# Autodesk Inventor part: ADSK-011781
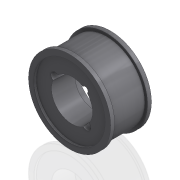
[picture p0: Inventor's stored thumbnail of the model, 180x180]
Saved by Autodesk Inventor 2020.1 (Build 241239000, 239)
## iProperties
Created: 1999-11
Part Number: ADSK-011781
Material: Acier (alliage faible hypertrempé)
Document SubType Name: Modeling
Designer: dmcquary
Density: 7.84 g/cm^3
Appearance: Metal-Steel(Polish)
Mass: 1096.04 g
Surface Area: 358.582 cm^2
Volume: 139.801 cm^3
Control State: 0
Master: False
Checked Out: False
Shininess: 0.0
Length Units: 11269
Angle Units: 11279
Time Units: 11290
Mass Units: 11283
Length Display Precision: 3
Angle Display Precision: 2
Compacted: True
Dimensions: 95,2x95,2x47,2 mm
Mass: 1,096 kg
DocNumber: ADSK-011781.ipt
Folder: 01 - Themengebiete\Simplification\01 - Packaging machine\
VDS_Category: 3D Komponenten
Density: 0.0
Volumn: 0.0
Area: 0.0
PropertySet Name: Model Information
Author: dmcquary
Revision Number: -
Title: belt wheel
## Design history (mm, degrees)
node "Solide1"
  node "Extrusion1" dims "d1" = 25.4, "d2" = 0
  node "Extrusion2" dims "d3" = 25.4, "d4" = -4 deg
  node "Extrusion4" dims "d16" = 2.794, "d17" = 0
  node "Extrusion5" dims "d20" = 19.05, "d21" = 0
  node "Hole2" dims "d26" = 10, "d27" = 9.525, "d28" = 6.35, "d29" = 60 deg, "d30" = 19.05, "d31" = 118 deg, "d52" = 6
  node "Hole3" dims "d33" = 6.6, "d34" = 9.525, "d35" = 6.35, "d36" = 60 deg, "d37" = 19.05, "d38" = 118 deg, "d51" = 6
  node "Extrusion6" dims "d44" = 1.778, "d45" = 0
  node "Extrusion7" dims "d46" = 14.478, "d47" = 0
sketch "Sketch2"
  geometry: C1 r 23.812 at (0, 0); C2 r 44.463 at (0, 0) reference
  constraints: 1 centre point, 1 coincident
  dimensions: "d22" = 47.625 diameter of C1
workplane "Arbeitsebene3"
workaxis "Work Axis3"
workplane "Work Plane2"
node "Corps solides"
node "Corps surfaciques"
sketch "Sketch1"
  geometry: C1 r 44.463 at (0, 0); 1 further point
  constraints: 1 centre point, 1 coincident
  dimensions: "d0" = 88.9254 diameter of C1
sketch "Sketch6"
  geometry: C1 r 44.463 at (0, 0) reference; C2 r 41.275 at (0, 0); C3 r 47.625 at (0, 0)
  constraints: 2 centre point, 2 coincident
  dimensions: "d14" = 95.25 diameter of C3; "d15" = 82.55 diameter of C2
sketch "Sketch7"
  geometry: C1 r 41.275 at (0, 0); C2 r 47.625 at (0, 0); 3 further points
  constraints: 2 centre point, 2 coincident, 1 other
  dimensions: "d18" = 95.25 diameter of C2; "d19" = 82.55 diameter of C1
sketch "Sketch8"
  geometry: L1 (-66.675, 0)-(66.675, 0) reference; L2 (-19.531, 13.623)-(0, 0); L3 (0, 0)-(16.874, -16.801); C1 r 41.275 at (0, 0) reference; A1 r 23.812 centre (0, 0) between (-19.531, 13.623) and (16.874, -16.801) reference
  constraints: 4 end point, 2 point on circle
  dimensions: "d48" = 34.8953 deg angle of L1 L2; "d49" = 44.8757 deg angle of L1 L3
sketch "Sketch10"
  geometry: L1 (0, 0)-(15.283, 18.261); L2 (-66.675, 0)-(66.675, 0) reference; C1 r 41.275 at (0, 0) reference; A1 r 23.812 centre (0, 0) between (20.011, -12.907) and (-16.256, 17.401) reference
  constraints: 2 end point, 1 point on circle
  dimensions: "d50" = 50.0741 deg angle of L1 L2
sketch "Sketch12"
  geometry: C1 r 47.625 at (0, 0) reference; C2 r 44.463 at (0, 0) reference
sketch "Sketch13"
  geometry: C1 r 47.625 at (0, 0) reference; C2 r 44.463 at (0, 0) reference
other parameters: "d43" = -23.01875
